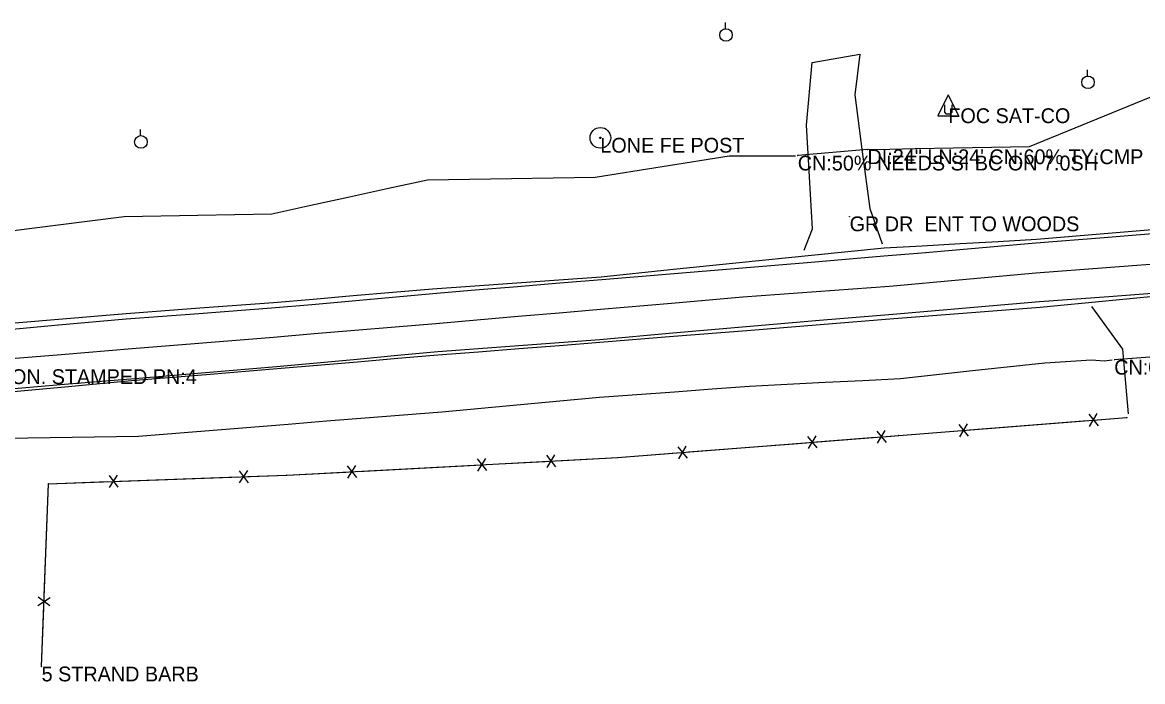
# Model space of a CAD drawing. Extents: x 1138803 to 1169983, y 1655906 to 1658226.
# Drawn here: x 1142745 to 1143123.5, y 1657524.3 to 1657747 of the extents above; entities that cross this region are included whole.
import ezdxf

# ---------------------------------------------------------------- set-up
doc = ezdxf.new("R2010")
doc.units = 0
for name, color, linetype in [('S_DITCHLINE', 7, 'Continuous'), ('S_DRG_PT_SYM', 7, 'Continuous'), ('S_EDGE_PAVEMENT', 7, 'Continuous'), ('S_FENCE', 7, 'Continuous'), ('S_FENCE_ANNOT', 7, 'Continuous'), ('S_GRAVEL_ROAD', 7, 'Continuous'), ('S_MSC_PT_SYM', 7, 'Continuous'), ('S_PAVEMENT_CROWN', 7, 'Continuous'), ('S_PRIMARY_CTL_ANNOT', 7, 'Continuous'), ('S_SHOULDER', 7, 'Continuous'), ('S_SIDE_DRAIN', 7, 'Continuous'), ('S_SIDE_DRAIN_ANNOT', 7, 'Continuous'), ('S_SURVEY_TEXT_ANNOT', 7, 'Continuous'), ('S_UNDERGROUND_CABLE', 7, 'Continuous'), ('S_UTILITY_POLE', 7, 'Continuous'), ('S_UTILITY_POLE_ANNOT', 7, 'Continuous')]:
    doc.layers.add(name, color=color, linetype=linetype)

msp = doc.modelspace()

# ---------------------------------------------------------------- linework, layer by layer
at = {"layer": 'S_DITCHLINE'}
for points in [[(1143030.92, 1657704.21), (1143033.86, 1657704.13), (1143046.72, 1657704.38), (1143059.59, 1657704.63), (1143072.45, 1657704.89), (1143085.32, 1657705.14), (1143105.7, 1657713.44), (1143126.07, 1657721.75), (1143132.06, 1657721.81)], [(1143006.22, 1657701.83), (1142983.78, 1657701.81), (1142961.17, 1657698.23), (1142938.56, 1657694.65), (1142924.4, 1657694.42), (1142910.24, 1657694.2), (1142896.08, 1657693.97), (1142881.92, 1657693.74), (1142868.75, 1657690.88), (1142855.58, 1657688.01), (1142842.41, 1657685.14), (1142829.24, 1657682.28), (1142804.29, 1657681.83), (1142779.34, 1657681.38), (1142757.03, 1657678.56), (1142734.73, 1657675.74)], [(1143113.27, 1657632.91), (1143110.56, 1657632.61), (1143106.23, 1657632.86), (1143090.44, 1657631.9), (1143066.07, 1657629.26), (1143041.69, 1657626.62), (1143028.95, 1657625.96), (1143016.21, 1657625.31), (1143003.46, 1657624.65), (1142990.72, 1657623.99), (1142978.03, 1657623.06), (1142965.33, 1657622.13), (1142952.64, 1657621.19), (1142939.95, 1657620.26), (1142926.64, 1657619.04), (1142913.34, 1657617.83), (1142900.03, 1657616.61), (1142886.73, 1657615.39), (1142873.75, 1657614.35), (1142860.78, 1657613.31), (1142847.8, 1657612.27), (1142834.82, 1657611.23), (1142822.17, 1657610.2), (1142809.51, 1657609.17), (1142796.86, 1657608.14), (1142784.2, 1657607.11), (1142761.83, 1657606.77), (1142739.45, 1657606.43)]]:
    msp.add_lwpolyline(points, dxfattribs=at)
at = {"layer": 'S_DRG_PT_SYM'}
for points in [[(1143007, 1657702.01), (1143007, 1657702.06), (1143007, 1657702.01), (1143006.95, 1657702.01), (1143007, 1657702.01), (1143007, 1657701.96), (1143007, 1657702.01), (1143007.05, 1657702.01)], [(1143030.57, 1657704.14), (1143030.57, 1657704.19), (1143030.57, 1657704.14), (1143030.52, 1657704.14), (1143030.57, 1657704.14), (1143030.57, 1657704.09), (1143030.57, 1657704.14), (1143030.62, 1657704.14)], [(1143030.62, 1657704.12), (1143030.62, 1657704.17), (1143030.62, 1657704.12), (1143030.57, 1657704.12), (1143030.62, 1657704.12), (1143030.62, 1657704.07), (1143030.62, 1657704.12), (1143030.67, 1657704.12)], [(1143113.93, 1657633.03), (1143113.93, 1657633.08), (1143113.93, 1657633.03), (1143113.88, 1657633.03), (1143113.93, 1657633.03), (1143113.93, 1657632.98), (1143113.93, 1657633.03), (1143113.98, 1657633.03)]]:
    msp.add_lwpolyline(points, dxfattribs=at)
at = {"layer": 'S_EDGE_PAVEMENT'}
for points in [[(1143133.64, 1657676.19), (1143110.57, 1657674.3), (1143087.49, 1657672.41), (1143074.64, 1657671.31), (1143061.78, 1657670.21), (1143048.93, 1657669.12), (1143036.07, 1657668.02), (1143011.52, 1657665.96), (1142986.97, 1657663.91), (1142963.91, 1657661.99), (1142940.84, 1657660.08), (1142926.56, 1657658.9), (1142912.28, 1657657.71), (1142898, 1657656.53), (1142883.73, 1657655.34), (1142870.07, 1657654.11), (1142856.42, 1657652.89), (1142842.77, 1657651.66), (1142829.12, 1657650.43), (1142804.59, 1657648.6), (1142780.06, 1657646.77), (1142757.17, 1657644.69), (1142734.28, 1657642.61)], [(1143135.55, 1657656.09), (1143112.14, 1657654.33), (1143088.72, 1657652.58), (1143063.92, 1657650.49), (1143039.12, 1657648.39), (1143014.33, 1657646.27), (1142989.54, 1657644.15), (1142964.81, 1657641.99), (1142940.07, 1657639.83), (1142926.41, 1657638.8), (1142912.74, 1657637.77), (1142899.07, 1657636.74), (1142885.4, 1657635.71), (1142871.77, 1657634.44), (1142858.13, 1657633.18), (1142844.5, 1657631.92), (1142830.86, 1657630.65), (1142806.91, 1657628.64), (1142782.95, 1657626.62), (1142759.24, 1657624.64), (1142735.53, 1657622.65)]]:
    msp.add_lwpolyline(points, dxfattribs=at)
at = {"layer": 'S_FENCE'}
for p, q in [((1143105.31, 1657614.62), (1143108.49, 1657610.76)), ((1143105.31, 1657614.62), (1143108.49, 1657610.76)), ((1143105.63, 1657610.53), (1143108.17, 1657614.84)), ((1143105.63, 1657610.53), (1143108.17, 1657614.84)), ((1143041.11, 1657607.47), (1143118.21, 1657613.59)), ((1143061.45, 1657611.14), (1143064.63, 1657607.28)), ((1143061.45, 1657611.14), (1143064.63, 1657607.28)), ((1143061.77, 1657607.06), (1143064.31, 1657611.37)), ((1143061.77, 1657607.06), (1143064.31, 1657611.37)), ((1142946.12, 1657600.02), (1143041.11, 1657607.47)), ((1143010.32, 1657607.11), (1143013.49, 1657603.25)), ((1143010.32, 1657607.11), (1143013.49, 1657603.25)), ((1143010.64, 1657603.03), (1143013.17, 1657607.33)), ((1143010.64, 1657603.03), (1143013.17, 1657607.33)), ((1143033.67, 1657608.94), (1143036.85, 1657605.08)), ((1143033.67, 1657608.94), (1143036.85, 1657605.08)), ((1143033.99, 1657604.86), (1143036.53, 1657609.17)), ((1143033.99, 1657604.86), (1143036.53, 1657609.17)), ((1142966.46, 1657603.67), (1142969.64, 1657599.81)), ((1142966.46, 1657603.67), (1142969.64, 1657599.81)), ((1142966.78, 1657599.58), (1142969.32, 1657603.89)), ((1142966.78, 1657599.58), (1142969.32, 1657603.89)), ((1142834.33, 1657594.04), (1142946.12, 1657600.02)), ((1142898.69, 1657599.53), (1142901.78, 1657595.59)), ((1142898.69, 1657599.53), (1142901.78, 1657595.59)), ((1142898.91, 1657595.44), (1142901.56, 1657599.68)), ((1142898.91, 1657595.44), (1142901.56, 1657599.68)), ((1142922.09, 1657600.78), (1142925.18, 1657596.85)), ((1142922.09, 1657600.78), (1142925.18, 1657596.85)), ((1142922.31, 1657596.69), (1142924.96, 1657600.94)), ((1142922.31, 1657596.69), (1142924.96, 1657600.94)), ((1142818.25, 1657595.51), (1142821.26, 1657591.52)), ((1142818.25, 1657595.51), (1142821.26, 1657591.52)), ((1142818.4, 1657591.42), (1142821.12, 1657595.61)), ((1142818.4, 1657591.42), (1142821.12, 1657595.61)), ((1142854.76, 1657597.18), (1142857.84, 1657593.24)), ((1142854.76, 1657597.18), (1142857.84, 1657593.24)), ((1142854.98, 1657593.09), (1142857.62, 1657597.33)), ((1142854.98, 1657593.09), (1142857.62, 1657597.33)), ((1142751.48, 1657529.38), (1142753.8, 1657591.16)), ((1142753.8, 1657591.16), (1142834.33, 1657594.04)), ((1142774.28, 1657593.94), (1142777.29, 1657589.95)), ((1142774.28, 1657593.94), (1142777.29, 1657589.95)), ((1142774.43, 1657589.85), (1142777.15, 1657594.04)), ((1142774.43, 1657589.85), (1142777.15, 1657594.04)), ((1142750.21, 1657550), (1142754.41, 1657552.72)), ((1142750.21, 1657550), (1142754.41, 1657552.72)), ((1142754.3, 1657549.85), (1142750.31, 1657552.87)), ((1142754.3, 1657549.85), (1142750.31, 1657552.87))]:
    msp.add_line(p, q, dxfattribs=at)
for points in [[(1143065.03, 1657609.37), (1143104.9, 1657612.53)], [(1143065.03, 1657609.37), (1143104.9, 1657612.53)], [(1143108.33, 1657612.8), (1143118.21, 1657613.59)], [(1143108.33, 1657612.8), (1143118.21, 1657613.59)], [(1143013.33, 1657605.29), (1143033.27, 1657606.86)], [(1143013.33, 1657605.29), (1143033.27, 1657606.86)], [(1143037.26, 1657607.17), (1143041.11, 1657607.47)], [(1143037.26, 1657607.17), (1143041.11, 1657607.47)], [(1143041.11, 1657607.47), (1143061.05, 1657609.05)], [(1143041.11, 1657607.47), (1143061.05, 1657609.05)], [(1142970.04, 1657601.89), (1143009.91, 1657605.02)], [(1142970.04, 1657601.89), (1143009.91, 1657605.02)], [(1142925.63, 1657598.92), (1142946.12, 1657600.02)], [(1142925.63, 1657598.92), (1142946.12, 1657600.02)], [(1142946.12, 1657600.02), (1142966.06, 1657601.58)], [(1142946.12, 1657600.02), (1142966.06, 1657601.58)], [(1142834.33, 1657594.04), (1142854.3, 1657595.1)], [(1142834.33, 1657594.04), (1142854.3, 1657595.1)], [(1142858.3, 1657595.32), (1142898.24, 1657597.46)], [(1142858.3, 1657595.32), (1142898.24, 1657597.46)], [(1142901.67, 1657597.64), (1142921.64, 1657598.71)], [(1142901.67, 1657597.64), (1142921.64, 1657598.71)], [(1142752.38, 1657553.36), (1142753.8, 1657591.16)], [(1142752.38, 1657553.36), (1142753.8, 1657591.16)], [(1142753.8, 1657591.16), (1142773.79, 1657591.87)], [(1142753.8, 1657591.16), (1142773.79, 1657591.87)], [(1142777.78, 1657592.02), (1142817.76, 1657593.44)], [(1142777.78, 1657592.02), (1142817.76, 1657593.44)], [(1142821.19, 1657593.57), (1142834.33, 1657594.04)], [(1142821.19, 1657593.57), (1142834.33, 1657594.04)], [(1142751.48, 1657529.38), (1142752.23, 1657549.36)], [(1142751.48, 1657529.38), (1142752.23, 1657549.36)]]:
    msp.add_lwpolyline(points, dxfattribs=at)
for radius in [3.49, 0.247, 0.0349]:
    msp.add_circle((1142940.29, 1657708.03), radius, dxfattribs=at)
at = {"layer": 'S_GRAVEL_ROAD'}
for points in [[(1143009.19, 1657670.09), (1143011.98, 1657677.31), (1143010.99, 1657694.84), (1143009.99, 1657712.36), (1143011.88, 1657733.49), (1143027.92, 1657736.35), (1143026.25, 1657722.53), (1143028.79, 1657703.33), (1143031.34, 1657684.12), (1143035.54, 1657672.21)], [(1143118.72, 1657614.73), (1143116.81, 1657636.62), (1143106.38, 1657651.01)]]:
    msp.add_lwpolyline(points, dxfattribs=at)
at = {"layer": 'S_MSC_PT_SYM'}
for points in [[(1143024.52, 1657681.47), (1143024.52, 1657681.52), (1143024.52, 1657681.47), (1143024.47, 1657681.47), (1143024.52, 1657681.47), (1143024.52, 1657681.42), (1143024.52, 1657681.47), (1143024.57, 1657681.47)], [(1143118.21, 1657613.59), (1143118.21, 1657613.64), (1143118.21, 1657613.59), (1143118.16, 1657613.59), (1143118.21, 1657613.59), (1143118.21, 1657613.54), (1143118.21, 1657613.59), (1143118.26, 1657613.59)], [(1143041.11, 1657607.47), (1143041.11, 1657607.52), (1143041.11, 1657607.47), (1143041.06, 1657607.47), (1143041.11, 1657607.47), (1143041.11, 1657607.42), (1143041.11, 1657607.47), (1143041.16, 1657607.47)], [(1142946.12, 1657600.02), (1142946.12, 1657600.07), (1142946.12, 1657600.02), (1142946.07, 1657600.02), (1142946.12, 1657600.02), (1142946.12, 1657599.97), (1142946.12, 1657600.02), (1142946.17, 1657600.02)], [(1142753.8, 1657591.16), (1142753.8, 1657591.21), (1142753.8, 1657591.16), (1142753.75, 1657591.16), (1142753.8, 1657591.16), (1142753.8, 1657591.11), (1142753.8, 1657591.16), (1142753.85, 1657591.16)], [(1142834.33, 1657594.04), (1142834.33, 1657594.09), (1142834.33, 1657594.04), (1142834.28, 1657594.04), (1142834.33, 1657594.04), (1142834.33, 1657593.99), (1142834.33, 1657594.04), (1142834.38, 1657594.04)], [(1142751.48, 1657529.38), (1142751.48, 1657529.43), (1142751.48, 1657529.38), (1142751.43, 1657529.38), (1142751.48, 1657529.38), (1142751.48, 1657529.33), (1142751.48, 1657529.38), (1142751.53, 1657529.38)]]:
    msp.add_lwpolyline(points, dxfattribs=at)
at = {"layer": 'S_PAVEMENT_CROWN'}
msp.add_lwpolyline([(1143134.96, 1657665.96), (1143111.19, 1657664.11), (1143087.41, 1657662.26), (1143062.71, 1657660.05), (1143038, 1657657.84), (1143013.19, 1657656), (1142988.39, 1657654.16), (1142964.36, 1657652.09), (1142940.33, 1657650.03), (1142926.42, 1657648.83), (1142912.5, 1657647.63), (1142898.59, 1657646.43), (1142884.68, 1657645.23), (1142870.98, 1657644.08), (1142857.28, 1657642.92), (1142843.58, 1657641.77), (1142829.88, 1657640.61), (1142805.99, 1657638.69), (1142782.09, 1657636.76), (1142758.09, 1657634.76), (1142734.08, 1657632.76)], dxfattribs=at)
at = {"layer": 'S_SHOULDER'}
for points in [[(1143133.52, 1657677.55), (1143110.56, 1657675.61), (1143087.61, 1657673.67), (1143074.75, 1657672.93), (1143061.89, 1657672.2), (1143049.03, 1657671.46), (1143036.17, 1657670.72), (1143011.68, 1657668.28), (1142987.2, 1657665.84), (1142963.86, 1657663.4), (1142940.53, 1657660.97), (1142926.3, 1657659.95), (1142912.07, 1657658.92), (1142897.84, 1657657.9), (1142883.61, 1657656.87), (1142870.17, 1657655.74), (1142856.73, 1657654.6), (1142843.3, 1657653.46), (1142829.86, 1657652.32), (1142804.94, 1657650.45), (1142780.02, 1657648.57), (1142757.16, 1657646.66), (1142734.31, 1657644.74)], [(1143135.58, 1657655.19), (1143112.25, 1657652.94), (1143088.92, 1657650.69), (1143064.19, 1657648.77), (1143039.45, 1657646.85), (1143014.62, 1657644.86), (1142989.8, 1657642.87), (1142964.98, 1657640.88), (1142940.16, 1657638.89), (1142926.47, 1657637.81), (1142912.78, 1657636.73), (1142899.1, 1657635.65), (1142885.41, 1657634.57), (1142871.83, 1657633.42), (1142858.25, 1657632.27), (1142844.67, 1657631.12), (1142831.09, 1657629.97), (1142807.09, 1657628.01), (1142783.09, 1657626.04), (1142759.37, 1657623.84), (1142735.65, 1657621.63)]]:
    msp.add_lwpolyline(points, dxfattribs=at)
at = {"layer": 'S_SIDE_DRAIN'}
for p, q in [((1143030.57, 1657704.14), (1143007, 1657702.01)), ((1143030.62, 1657704.12), (1143030.57, 1657704.14)), ((1143137.27, 1657634.75), (1143113.93, 1657633.03))]:
    msp.add_line(p, q, dxfattribs=at)
at = {"layer": 'S_UNDERGROUND_CABLE'}
for p, q in [((1143057.87, 1657722.54), (1143054.34, 1657715.45)), ((1143057.87, 1657722.54), (1143061.35, 1657715.45)), ((1143056.66, 1657716.69), (1143056.66, 1657719.13)), ((1143057.28, 1657716.03), (1143056.66, 1657716.69)), ((1143059.03, 1657716.69), (1143058.49, 1657716.03)), ((1143059.03, 1657719.13), (1143059.03, 1657716.69)), ((1143054.34, 1657715.45), (1143061.35, 1657715.45)), ((1143058.49, 1657716.03), (1143057.28, 1657716.03))]:
    msp.add_line(p, q, dxfattribs=at)
at = {"layer": 'S_UTILITY_POLE'}
for p, q in [((1142982.63, 1657744.93), (1142982.63, 1657747.04)), ((1143104.95, 1657728.93), (1143104.95, 1657731.04)), ((1142784.93, 1657708.78), (1142784.93, 1657710.88))]:
    msp.add_line(p, q, dxfattribs=at)
for centre in [(1142982.75, 1657742.79), (1143105.07, 1657726.79), (1142785.05, 1657706.64)]:
    msp.add_circle(centre, 2.13, dxfattribs=at)

# ---------------------------------------------------------------- texts
at = {"layer": 'S_FENCE_ANNOT'}
for s, p in [('LONE FE POST', (1142940.29, 1657703.03)), ('5 STRAND BARB', (1142751.48, 1657524.38))]:
    msp.add_text(s, height=5, dxfattribs=at).set_placement(p)
at = {"layer": 'S_PRIMARY_CTL_ANNOT'}
msp.add_text('PD:ARDOT STD. MON. STAMPED PN:4', height=5, dxfattribs=at).set_placement((1142682.09, 1657624.83))
at = {"layer": 'S_SIDE_DRAIN_ANNOT'}
for s, p in [('CN:50% NEEDS SI BC ON 7.0SH', (1143007, 1657697.01)), ('DI:24" LN:24\' CN:60% TY:CMP', (1143030.57, 1657699.14)), ('CN:0%', (1143113.93, 1657628.03))]:
    msp.add_text(s, height=5, dxfattribs=at).set_placement(p)
at = {"layer": 'S_SURVEY_TEXT_ANNOT'}
msp.add_text('GR DR  ENT TO WOODS', height=5, dxfattribs=at).set_placement((1143024.52, 1657676.47))
at = {"layer": 'S_UTILITY_POLE_ANNOT'}
msp.add_text('FOC SAT-CO', height=5, dxfattribs=at).set_placement((1143057.87, 1657713.01))

doc.saveas('drawing.dxf')
